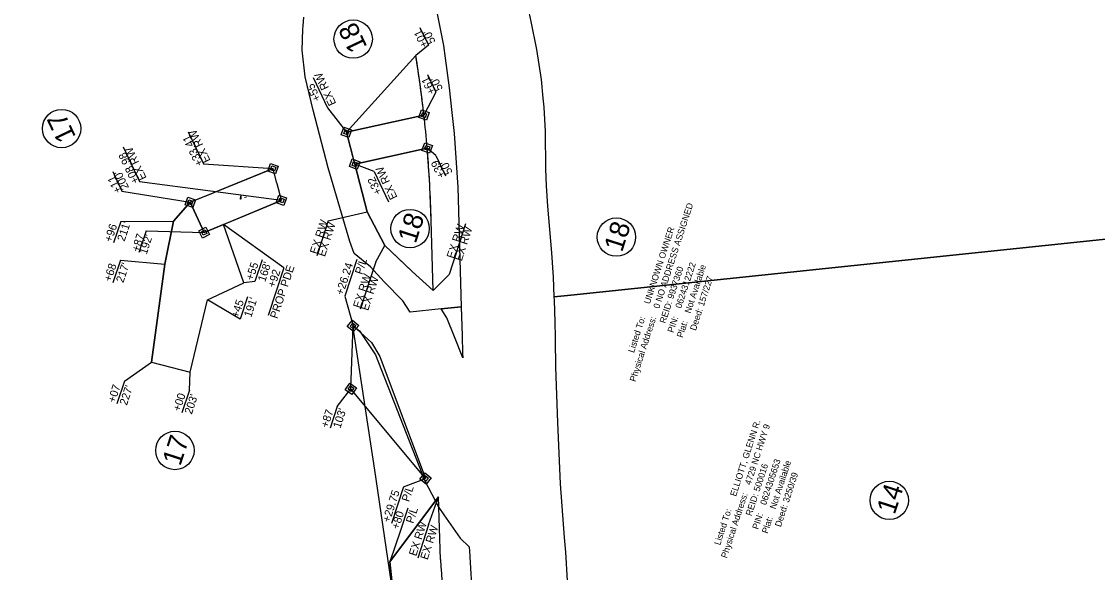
# Model space of a CAD drawing. Extents: x 1019969 to 1024963, y 638146 to 643978.
# Drawn here: x 1022801 to 1023474, y 640749 to 641093 of the extents above; entities that cross this region are included whole.
import ezdxf

# ---------------------------------------------------------------- set-up
doc = ezdxf.new("R2010")
doc.units = 0
for name, color, linetype in [('Old_Level_30', 7, 'Continuous'), ('Pattern 1', 7, 'Continuous'), ('Pattern 2', 7, 'Continuous'), ('Pattern 4', 7, 'Continuous'), ('Pattern 5', 7, 'Continuous'), ('Pattern 6', 7, 'Continuous'), ('Prop Easement Construction', 7, 'Continuous'), ('Prop Easement Construction Station Offsets', 7, 'Continuous'), ('Prop Easement Permanent Drainage', 7, 'Continuous'), ('Prop Easement Permanent Drainage Station Offsets', 7, 'Continuous'), ('Prop Easement Permanent Utility', 7, 'Continuous'), ('Prop Easement Permanent Utility Station Offsets', 7, 'Continuous'), ('Prop Easement Temporary Drainage', 7, 'Continuous'), ('Prop Easement Temporary Drainage Station Offsets', 7, 'Continuous'), ('Prop Parcel Number CELL', 7, 'Continuous'), ('Prop Parcel Owner Text', 7, 'Continuous'), ('Prop ROW Marker CELL', 7, 'Continuous'), ('Prop ROW Permanent Easement CELL', 7, 'Continuous'), ('Prop ROW RW Lines', 7, 'Continuous')]:
    doc.layers.add(name, color=color, linetype=linetype)

msp = doc.modelspace()

# ---------------------------------------------------------------- linework, layer by layer
at = {"layer": 'Old_Level_30'}
for points in [[(1023560.21, 640965.29), (1023144.57, 640921.75), (1023134.28, 640920.67), (1023133.69, 640933), (1023132.63, 640948.13), (1023130.19, 640977.38), (1023129.38, 640990.06), (1023129, 641000.63), (1023128.81, 641024), (1023127.88, 641039.25), (1023127.38, 641044.75), (1023126.31, 641056.5), (1023123.31, 641075.31), (1023119.88, 641092.63), (1023116.63, 641107.44)], [(1023061.16, 641097.58), (1023065.12, 641077.76), (1023066.19, 641069.81), (1023068.66, 641051.33), (1023070.33, 641035.97), (1023071.78, 641022.71), (1023074.02, 640989.23), (1023076.16, 640914.57), (1023063.53, 640913.25), (1023044.18, 640911.23), (1023039.68, 640918.29), (1023027.96, 640930), (1023019.54, 640939.51), (1023009.24, 640947.69), (1023006.5, 640955.23), (1022993.07, 641001.3), (1022990.32, 641011.77), (1022987.61, 641022.09), (1022983.64, 641037.24), (1022978.57, 641058.21), (1022976.78, 641074.72), (1022977.15, 641088), (1022977.33, 641090.02), (1022977.84, 641095.42)], [(1023143.52, 640725.34), (1023141.45, 640761.25), (1023140.63, 640770.38), (1023138.19, 640803.94), (1023136.38, 640842.13), (1023135.31, 640876.69), (1023135, 640894.14), (1023134.98, 640895.34), (1023134.81, 640905), (1023134.38, 640918.62), (1023134.28, 640920.67), (1023144.57, 640921.75), (1023560.21, 640965.29)]]:
    msp.add_lwpolyline(points, dxfattribs=at)
for points in [[(1023076.98, 640885.53), (1023077.07, 640882.52), (1023071.92, 640895.67), (1023067.23, 640907.67), (1023063.53, 640913.25), (1023076.16, 640914.57), (1023076.68, 640896.33)], [(1023055.36, 640605.4), (1023041.41, 640595.86), (1023038.8, 640682.3), (1023033.32, 640736.02), (1023022.08, 640812.39), (1023008.43, 640902.89), (1023012.66, 640899.52), (1023022.6, 640884.5), (1023053.35, 640805.87), (1023062.14, 640789.09), (1023065.25, 640784.66), (1023075.54, 640770), (1023081.17, 640764.56), (1023081.43, 640758.68), (1023081.46, 640758.27), (1023083.03, 640733.83), (1023084.28, 640714.36), (1023085.72, 640703.43), (1023087.55, 640681.83), (1023089.55, 640665.32), (1023093.54, 640641.91), (1023094.86, 640636.35), (1023095.68, 640632.94)]]:
    msp.add_lwpolyline(points, close=True, dxfattribs=at)
at = {"layer": 'Pattern 1'}
for p, q in [((1022906.84, 640979.76), (1022896.33, 640968.04)), ((1022915.54, 640960.88), (1022906.84, 640979.76)), ((1022896.33, 640968.04), (1022891.06, 640941.21)), ((1022927.68, 640965.94), (1022915.54, 640960.88)), ((1022940.39, 640929.53), (1022927.68, 640965.94)), ((1022891.06, 640941.21), (1022882.69, 640879.97)), ((1022917.66, 640918.92), (1022940.39, 640929.53)), ((1022906.87, 640873.61), (1022917.66, 640918.92)), ((1022882.69, 640879.97), (1022906.87, 640873.61))]:
    msp.add_line(p, q, dxfattribs=at)
at = {"layer": 'Pattern 2'}
for p, q in [((1023052.83, 641034.25), (1023004.39, 641023.5)), ((1023004.39, 641023.5), (1023004.39, 641023.5)), ((1023004.39, 641023.5), (1023009.49, 641003.98)), ((1023013.63, 641004.51), (1023054.86, 641013.68)), ((1022957.67, 641000.47), (1022924.87, 640987.1)), ((1022958.63, 641000.86), (1022957.67, 641000.47)), ((1022960.83, 640992.45), (1022958.63, 641000.86)), ((1023009.49, 641003.98), (1023009.59, 641003.61)), ((1023009.59, 641003.61), (1023010.83, 641003.89)), ((1022924.87, 640987.1), (1022919.04, 640984.73)), ((1022961.11, 640991.36), (1022960.83, 640992.45)), ((1022963.82, 640981.01), (1022961.11, 640991.36)), ((1022906.84, 640979.76), (1022915.54, 640960.88)), ((1022915.54, 640960.88), (1022963.23, 640980.76)), ((1022938.35, 640981.69), (1022938.54, 640983.73)), ((1022938.37, 640981.63), (1022938.35, 640981.69)), ((1022938.54, 640983.73), (1022938.37, 640981.63)), ((1022940.86, 640982.7), (1022940.89, 640982.71)), ((1022940.89, 640982.63), (1022940.86, 640982.7)), ((1022940.89, 640982.71), (1022940.89, 640982.63)), ((1022941.85, 640983.12), (1022941.88, 640983.13)), ((1022941.87, 640983.08), (1022941.85, 640983.12)), ((1022941.88, 640983.13), (1022941.87, 640983.08)), ((1022942.9, 640983.57), (1022942.92, 640983.58)), ((1022942.92, 640983.53), (1022942.9, 640983.57)), ((1022942.92, 640983.58), (1022942.92, 640983.53)), ((1022963.23, 640980.76), (1022963.82, 640981.01))]:
    msp.add_line(p, q, dxfattribs=at)
for points in [[(1023010.83, 641003.89), (1023010.95, 641003.91), (1023013.63, 641004.51)], [(1022919.04, 640984.73), (1022919, 640984.71), (1022906.84, 640979.76)]]:
    msp.add_lwpolyline(points, dxfattribs=at)
msp.add_arc((1022281.11, 640947.7), 776.56, 4.87366, 6.39866, dxfattribs=at)
at = {"layer": 'Pattern 4'}
msp.add_lwpolyline([(1023053.83, 640807.28), (1023007.18, 640863.29), (1023008.53, 640902.58), (1023019.99, 640892.11), (1023025.25, 640883.52)], close=True, dxfattribs=at)
at = {"layer": 'Pattern 6'}
for p, q in [((1023047.74, 641071.44), (1023004.39, 641023.5)), ((1023004.39, 641023.5), (1023052.83, 641034.25)), ((1023052.83, 641034.25), (1023052.83, 641034.25)), ((1023054.86, 641013.68), (1023009.59, 641003.61)), ((1023054.86, 641013.68), (1023054.86, 641013.68)), ((1023058.56, 640924.67), (1023057.39, 640968.47)), ((1023031.59, 640755.22), (1023031.59, 640755.22)), ((1023031.59, 640755.22), (1023031.59, 640755.22)), ((1023031.59, 640755.22), (1023034.01, 640730.95))]:
    msp.add_line(p, q, dxfattribs=at)
for points in [[(1023009.59, 641003.61), (1023017.38, 640973.78), (1023028.32, 640952.87), (1023040.42, 640941.28)], [(1023040.42, 640941.28), (1023045.45, 640936.46), (1023058.56, 640924.67)], [(1023063.24, 640756.72), (1023062.01, 640795.8), (1023031.59, 640755.22)]]:
    msp.add_lwpolyline(points, dxfattribs=at)
for centre, radius, start, end in [((1022417.81, 640969.29), 638.16, 8.97292, 9.21132), ((1022281.11, 640947.7), 776.56, 6.39866, 8.97292), ((1022281.11, 640947.7), 776.56, 1.53224, 4.87366), ((1023968.6, 640799.49), 906.36, 182.70435, 191.65074)]:
    msp.add_arc(centre, radius, start, end, dxfattribs=at)
at = {"layer": 'Prop Easement Construction'}
for p, q in [((1023004.39, 641023.5), (1023047.74, 641071.44)), ((1023017.38, 640973.78), (1023009.59, 641003.61)), ((1023057.39, 640968.47), (1023056.24, 640994.75)), ((1023028.32, 640952.87), (1023017.38, 640973.78)), ((1023058.56, 640924.67), (1023057.39, 640968.47)), ((1023031.59, 640755.22), (1023062.01, 640795.8)), ((1023034.01, 640730.95), (1023031.59, 640755.22)), ((1023034.01, 640730.95), (1023031.59, 640755.22))]:
    msp.add_line(p, q, dxfattribs=at)
msp.add_lwpolyline([(1023058.56, 640924.67), (1023045.45, 640936.46), (1023028.32, 640952.87)], dxfattribs=at)
for start, end in [(6.39866, 9.16889), (3.47362, 4.87366)]:
    msp.add_arc((1022281.11, 640947.7), 776.56, start, end, dxfattribs=at)
at = {"layer": 'Prop Easement Construction Station Offsets'}
for p, q in [((1023050.37, 641089.05), (1023055.65, 641077.91)), ((1022993.09, 640968.29), (1022985.94, 640946.29)), ((1023078.78, 640966.23), (1023068.51, 640934.64)), ((1023022.7, 640942.66), (1023013.09, 640913.08)), ((1023042.76, 640788.72), (1023038.23, 640774.79)), ((1023055.74, 640778.28), (1023049, 640757.57))]:
    msp.add_line(p, q, dxfattribs=at)
for points in [[(1023055.65, 641077.91), (1023047.74, 641071.44)], [(1022993.09, 640968.29), (1023017.38, 640973.78)], [(1023022.7, 640942.66), (1023028.32, 640952.87)], [(1023068.51, 640934.64), (1023058.56, 640924.67)], [(1023055.74, 640778.28), (1023062.01, 640795.8)], [(1023038.23, 640774.79), (1023031.59, 640755.22)]]:
    msp.add_lwpolyline(points, dxfattribs=at)
at = {"layer": 'Prop Easement Permanent Drainage'}
for p, q in [((1023052.83, 641034.25), (1023004.39, 641023.5)), ((1023009.59, 641003.61), (1023004.39, 641023.5)), ((1023054.86, 641013.68), (1023009.59, 641003.61)), ((1022906.84, 640979.76), (1022958.63, 641000.86)), ((1022906.84, 640979.76), (1022915.54, 640960.88)), ((1022915.54, 640960.88), (1022963.82, 640981.01))]:
    msp.add_line(p, q, dxfattribs=at)
msp.add_arc((1022281.11, 640947.7), 776.56, 4.87366, 6.39866, dxfattribs=at)
at = {"layer": 'Prop Easement Permanent Drainage Station Offsets'}
for p, q in [((1022983.59, 641057.68), (1022992.54, 641038.79)), ((1023054.97, 641059.7), (1023060.24, 641048.56)), ((1022905.59, 641023.78), (1022915.1, 641003.71)), ((1022864.91, 641014.49), (1022875.17, 640992.83)), ((1023060.31, 641009.01), (1023066.32, 640996.33)), ((1022858.43, 640998.94), (1022864.19, 640986.78)), ((1023021.82, 640999.05), (1023030.77, 640980.16)), ((1022879.22, 640961.9), (1022874.82, 640948.39))]:
    msp.add_line(p, q, dxfattribs=at)
for points in [[(1023060.24, 641048.56), (1023052.83, 641034.25)], [(1022992.54, 641038.79), (1023004.39, 641023.5)], [(1023060.31, 641009.01), (1023054.86, 641013.68)], [(1022915.1, 641003.71), (1022958.63, 641000.86)], [(1023021.82, 640999.05), (1023009.59, 641003.61)], [(1022864.19, 640986.78), (1022906.84, 640979.76)], [(1022875.17, 640992.83), (1022963.82, 640981.01)], [(1022879.22, 640961.9), (1022915.54, 640960.88)]]:
    msp.add_lwpolyline(points, dxfattribs=at)
at = {"layer": 'Prop Easement Permanent Utility'}
for p, q in [((1023007.18, 640863.29), (1023008.53, 640902.58)), ((1023053.83, 640807.28), (1023007.18, 640863.29))]:
    msp.add_line(p, q, dxfattribs=at)
at = {"layer": 'Prop Easement Permanent Utility Station Offsets'}
for p, q in [((1023010.9, 640943.99), (1023003.46, 640921.09)), ((1022998.59, 640852.23), (1022994.17, 640838.63)), ((1023040.05, 640802.05), (1023032.64, 640779.23))]:
    msp.add_line(p, q, dxfattribs=at)
for points in [[(1023003.46, 640921.09), (1023008.53, 640902.58)], [(1022998.59, 640852.23), (1023007.18, 640863.29)], [(1023040.05, 640802.05), (1023053.83, 640807.28)]]:
    msp.add_lwpolyline(points, dxfattribs=at)
at = {"layer": 'Prop Easement Temporary Drainage'}
for p, q in [((1022896.33, 640968.04), (1022906.84, 640979.76)), ((1022891.06, 640941.21), (1022896.33, 640968.04)), ((1022940.39, 640929.53), (1022927.68, 640965.94)), ((1022882.69, 640879.97), (1022891.06, 640941.21)), ((1022917.66, 640918.92), (1022940.39, 640929.53)), ((1022906.87, 640873.61), (1022917.66, 640918.92)), ((1022882.69, 640879.97), (1022906.87, 640873.61))]:
    msp.add_line(p, q, dxfattribs=at)
at = {"layer": 'Prop Easement Temporary Drainage Station Offsets'}
for p, q in [((1022863.45, 640967.86), (1022859.01, 640954.42)), ((1022863.21, 640943.56), (1022858.54, 640929.4)), ((1022951.68, 640943.77), (1022947.26, 640930.38)), ((1022965.29, 640938.94), (1022955.45, 640909.15)), ((1022942.69, 640920.63), (1022938.11, 640906.76)), ((1022865.78, 640868.12), (1022861.05, 640853.8)), ((1022906.32, 640862.45), (1022901.66, 640848.35))]:
    msp.add_line(p, q, dxfattribs=at)
for points in [[(1022863.45, 640967.86), (1022896.33, 640968.04)], [(1022965.29, 640938.94), (1022927.68, 640965.94)], [(1022863.21, 640943.56), (1022891.06, 640941.21)], [(1022947.26, 640930.38), (1022940.39, 640929.53)], [(1022938.11, 640906.76), (1022917.66, 640918.92)], [(1022865.78, 640868.12), (1022882.69, 640879.97)], [(1022906.32, 640862.45), (1022906.87, 640873.61)]]:
    msp.add_lwpolyline(points, dxfattribs=at)
at = {"layer": 'Prop Parcel Number CELL'}
for p, q in [((1023008.62, 641081.72), (1023008.62, 641081.72)), ((1022826.5, 641025.83), (1022826.5, 641025.83)), ((1023044.18, 640963.37), (1023044.18, 640963.37)), ((1023173.08, 640958.03), (1023173.08, 640958.03)), ((1022897.28, 640824.76), (1022897.28, 640824.76)), ((1023343.52, 640793.59), (1023343.52, 640793.59))]:
    msp.add_line(p, q, dxfattribs=at)
for centre in [(1023008.62, 641081.72), (1022826.5, 641025.83), (1023044.18, 640963.37), (1023173.08, 640958.03), (1022897.28, 640824.76), (1023343.52, 640793.59)]:
    msp.add_circle(centre, 12, dxfattribs=at)
at = {"layer": 'Prop ROW Marker CELL'}
for p, q in [((1023052.83, 641034.25), (1023052.83, 641034.25)), ((1023004.39, 641023.5), (1023004.39, 641023.5)), ((1023054.86, 641013.68), (1023054.86, 641013.68)), ((1022958.63, 641000.86), (1022958.63, 641000.86)), ((1023009.59, 641003.61), (1023009.59, 641003.61)), ((1022906.84, 640979.76), (1022906.84, 640979.76)), ((1022963.82, 640981.01), (1022963.82, 640981.01)), ((1022915.54, 640960.88), (1022915.54, 640960.88)), ((1023008.53, 640902.58), (1023008.53, 640902.58)), ((1023007.18, 640863.29), (1023007.18, 640863.29)), ((1023053.83, 640807.28), (1023053.83, 640807.28))]:
    msp.add_line(p, q, dxfattribs=at)
at = {"layer": 'Prop ROW Permanent Easement CELL'}
for points in [[(1023049.57, 641032.71), (1023051.29, 641037.5), (1023056.08, 641035.79), (1023054.37, 641030.99)], [(1023051.2, 641033.48), (1023052.06, 641035.87), (1023054.45, 641035.02), (1023053.6, 641032.62)], [(1023001.14, 641021.96), (1023002.85, 641026.76), (1023007.65, 641025.04), (1023005.93, 641020.25)], [(1023002.77, 641022.73), (1023003.62, 641025.13), (1023006.02, 641024.27), (1023005.16, 641021.88)], [(1023051.6, 641012.14), (1023053.32, 641016.93), (1023058.11, 641015.22), (1023056.4, 641010.42)], [(1023053.23, 641012.91), (1023054.09, 641015.31), (1023056.48, 641014.45), (1023055.63, 641012.05)], [(1023006.34, 641002.07), (1023008.05, 641006.86), (1023012.84, 641005.15), (1023011.13, 641000.36)], [(1022955.38, 640999.32), (1022957.09, 641004.11), (1022961.88, 641002.4), (1022960.17, 640997.6)], [(1022957, 641000.09), (1022957.86, 641002.49), (1022960.26, 641001.63), (1022959.4, 640999.23)], [(1023007.96, 641002.84), (1023008.82, 641005.24), (1023011.22, 641004.38), (1023010.36, 641001.98)], [(1022903.59, 640978.22), (1022905.3, 640983.01), (1022910.1, 640981.3), (1022908.38, 640976.51)], [(1022905.22, 640978.99), (1022906.07, 640981.39), (1022908.47, 640980.53), (1022907.61, 640978.13)], [(1022960.56, 640979.47), (1022962.28, 640984.26), (1022967.07, 640982.55), (1022965.36, 640977.76)], [(1022962.19, 640980.24), (1022963.05, 640982.64), (1022965.44, 640981.78), (1022964.59, 640979.38)], [(1022912.12, 640961.99), (1022916.65, 640964.3), (1022918.96, 640959.76), (1022914.43, 640957.45)], [(1022913.83, 640961.43), (1022916.1, 640962.59), (1022917.25, 640960.32), (1022914.98, 640959.16)], [(1023008.87, 640899), (1023004.95, 640902.25), (1023008.2, 640906.17), (1023012.12, 640902.92)], [(1023008.7, 640900.79), (1023006.74, 640902.42), (1023008.37, 640904.38), (1023010.33, 640902.75)], [(1023006.59, 640866.84), (1023010.73, 640863.88), (1023007.77, 640859.74), (1023003.63, 640862.7)], [(1023006.89, 640865.07), (1023008.96, 640863.59), (1023007.48, 640861.52), (1023005.41, 640863)], [(1023050.25, 640806.9), (1023053.45, 640810.86), (1023057.41, 640807.66), (1023054.21, 640803.7)], [(1023052.04, 640807.09), (1023053.64, 640809.07), (1023055.62, 640807.47), (1023054.02, 640805.49)]]:
    msp.add_lwpolyline(points, close=True, dxfattribs=at)
at = {"layer": 'Prop ROW RW Lines'}
msp.add_arc((1022167.9, 640774.19), 948.09, 40.00236, 40.00236, dxfattribs=at)

# ---------------------------------------------------------------- texts
at = {"layer": 'Pattern 5'}
for s, rotation, p in [('0 NO ADDRESS ASSIGNED', 71.99034, (1023199.81, 640913.03)), ('UNKNOWN OWNER', 71.99034, (1023193.91, 640915.89)), ('9937360', 71.99034, (1023208.61, 640919.08)), ('0624312222', 71.99034, (1023213.54, 640913.22)), ('Not Available', 71.99034, (1023219.36, 640910.1)), ('157/227', 71.99034, (1023227.63, 640914.5)), ('REID:', 71.99034, (1023203.66, 640903.86)), ('Deed:', 71.99034, (1023222.68, 640899.29)), ('Listed To:', 71.99034, (1023184.01, 640885.46)), ('Physical Address:', 71.99034, (1023184.97, 640867.38)), ('PIN:', 71.99034, (1023208.59, 640898)), ('Plat:', 71.99034, (1023214.41, 640894.88)), ('ELLIOTT, GLENN R.', 71.9892, (1023247.76, 640795.74)), ('4729 NC HWY 9', 71.9892, (1023256.9, 640802.83)), ('0624305653', 71.9892, (1023266.51, 640790.36)), ('Not Available', 71.9892, (1023272.52, 640787.82)), ('500016', 71.9892, (1023262.41, 640798.77)), ('3250/39', 71.9892, (1023280.68, 640791.89)), ('Physical Address:', 71.9892, (1023242.06, 640757.19)), ('REID:', 71.9892, (1023257.46, 640783.55)), ('Listed To:', 71.9892, (1023237.86, 640765.31)), ('PIN:', 71.9892, (1023261.56, 640775.14)), ('Deed:', 71.9892, (1023275.73, 640776.67)), ('Plat:', 71.9892, (1023267.57, 640772.6))]:
    msp.add_text(s, height=4, rotation=rotation, dxfattribs=at).set_placement(p)
at = {"layer": 'Prop Easement Construction Station Offsets'}
for s, rotation, p in [('+01', 115.34303, (1023055.62, 641077.9)), ("50'", 115.34303, (1023060.19, 641080.06)), ('EX RW', 71.99034, (1022986.15, 640947.02)), ('EX RW', 71.99034, (1022990.95, 640945.46)), ('EX RW', 71.99034, (1023071.61, 640944.25)), ('EX RW', 71.99034, (1023076.41, 640942.68)), ('EX RW', 71.99034, (1023013.13, 640913.29)), ('EX RW', 71.99034, (1023017.93, 640911.73)), ('+80', 71.9892, (1023037.03, 640775.13)), ('P/L', 71.9892, (1023046.12, 640778.84)), ('EX RW', 71.9892, (1023047.97, 640758.44)), ('EX RW', 71.9892, (1023055.1, 640756.12))]:
    msp.add_text(s, height=5, rotation=rotation, dxfattribs=at).set_placement(p)
at = {"layer": 'Prop Easement Permanent Drainage Station Offsets'}
for s, rotation, p in [('+55', 115.34303, (1022988.58, 641044.22)), ('EX RW', 115.34303, (1022998.15, 641041.53)), ('+61', 115.34303, (1023060.22, 641048.55)), ("50'", 115.34303, (1023064.79, 641050.71)), ('+33.41', 115.34303, (1022915.08, 641003.7)), ('EX RW', 115.34303, (1022919.64, 641005.86)), ('EX RW', 115.34303, (1022879.71, 640994.98)), ('+08.98', 115.34303, (1022875.15, 640992.82)), ('EX RW', 115.34303, (1023036.38, 640982.9)), ('+39', 115.34303, (1023066.3, 640996.32)), ("50'", 115.34303, (1023070.86, 640998.48)), ('+11', 115.34303, (1022864.17, 640986.77)), ("200'", 115.34303, (1022868.73, 640988.94)), ('+32', 115.34303, (1023026.66, 640985.9)), ('+87', 71.99034, (1022874.8, 640948.4)), ("192'", 71.99034, (1022879.6, 640946.84))]:
    msp.add_text(s, height=5, rotation=rotation, dxfattribs=at).set_placement(p)
at = {"layer": 'Prop Easement Permanent Utility Station Offsets'}
for s, p in [('+26.24', (1023002.26, 640921.44)), ('P/L', (1023014.32, 640934.29)), ('+87', (1022992.85, 640838.6)), ("103'", (1023000.61, 640838.23)), ('+29.75', (1023031.39, 640779.43)), ('P/L', (1023043.47, 640792.35))]:
    msp.add_text(s, height=5, rotation=71.9892, dxfattribs=at).set_placement(p)
at = {"layer": 'Prop Easement Temporary Drainage Station Offsets'}
for s, p in [('+96', (1022857.73, 640954.51)), ("211'", (1022865.78, 640954.99)), ('+68', (1022857.37, 640929.84)), ("217'", (1022865.05, 640929.2)), ('+55', (1022946.01, 640930.58)), ("168'", (1022953.64, 640929.76)), ('PROP PDE', (1022961.24, 640906.73)), ('+92', (1022959.72, 640926.07)), ("191'", (1022944.94, 640907.51)), ('+45', (1022936.94, 640907.2)), ('+07', (1022859.85, 640854.15)), ("227'", (1022867.24, 640852.6)), ('+00', (1022900.49, 640848.79)), ("203'", (1022907.8, 640847.02))]:
    msp.add_text(s, height=5, rotation=71.73039, dxfattribs=at).set_placement(p)
at = {"layer": 'Prop Parcel Owner Text'}
for s, rotation, p in [('18', 115.34303, (1023017.64, 641076.87)), ('17', 115.34303, (1022835.65, 641020.72)), ('18', 71.99034, (1023047.64, 640953.5)), ('18', 71.99034, (1023176.54, 640948.16)), ('17', 71.99034, (1022900.65, 640814.58)), ('14', 71.9892, (1023346.88, 640784.25))]:
    msp.add_text(s, height=12.15, rotation=rotation, dxfattribs=at).set_placement(p)

doc.saveas('drawing.dxf')
